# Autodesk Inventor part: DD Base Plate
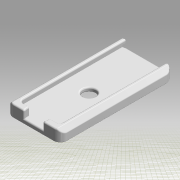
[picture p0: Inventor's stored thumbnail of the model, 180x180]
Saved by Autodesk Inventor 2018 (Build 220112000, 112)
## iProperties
Created: 2013-06
Part Number: DD Base Plate
Material: Generic
Description: STEP AP214
Document SubType Name: Modeling
Designer: johne
Appearance: Generic
Sending System: SolidWorks 2013
Preprocessor: SwSTEP 2.0
Title: Baseplate.STEP
Author: Asher
Revision Number: ANY
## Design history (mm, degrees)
feature "Body-Move_Copy1"
body "Solid1"
